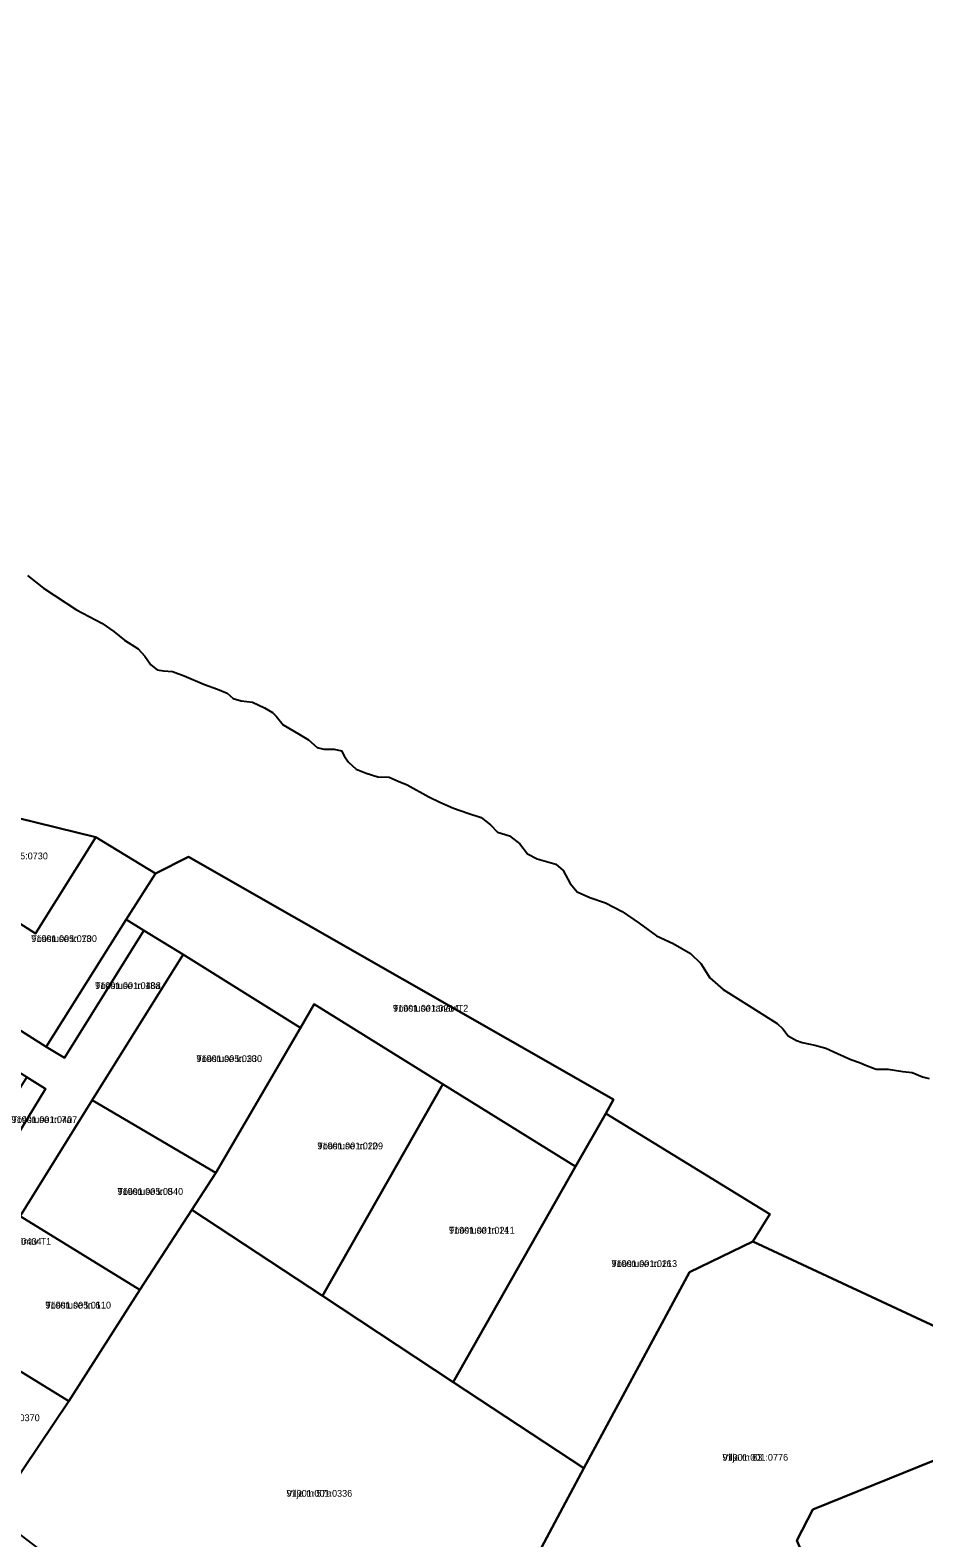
# Model space of a CAD drawing. Extents: x 675810 to 681273, y 6411190 to 6417565.
# Drawn here: x 679212.9 to 679410.2, y 6415637.7 to 6415970.5 of the extents above; entities that cross this region are included whole.
import ezdxf

# ---------------------------------------------------------------- set-up
doc = ezdxf.new("R2010")
doc.units = 0
for name, color, linetype in [('L_AADRESS', 7, 'Continuous'), ('PIIR', 7, 'Continuous'), ('TUNNUS', 7, 'Continuous')]:
    doc.layers.add(name, color=color, linetype=linetype)

msp = doc.modelspace()

# ---------------------------------------------------------------- linework, layer by layer
at = {"layer": 'PIIR'}
for points in [[(679418.32, 6415681.66), (679372.45, 6415703.1), (679376.15, 6415709.11), (679339.93, 6415731.36), (679341.68, 6415734.46), (679247.81, 6415787.97), (679240.52, 6415784.31), (679227.34, 6415792.31), (679201.2, 6415798.72), (679202.38, 6415803.59), (679204.44, 6415812.13), (679165.65, 6415822.55), (679175.65, 6415842.58), (679168.11, 6415879.95), (679127.82, 6415898.47), (679110.64, 6415865.76), (679105.26, 6415855.66), (678938.35, 6415931.63), (678872.23, 6415963.49), (678840.09, 6415967.49), (678816.91, 6415970.45)], [(679212.29, 6415850.08), (679215.84, 6415847.26), (679223.07, 6415842.49), (679228.71, 6415839.55), (679231.35, 6415837.72), (679233.71, 6415835.82), (679236.68, 6415833.88), (679238.2, 6415832.28), (679239.5, 6415830.35), (679240.87, 6415829.29), (679242.32, 6415829.02), (679244.28, 6415828.89), (679246.87, 6415827.94), (679251.36, 6415826.01), (679254.2, 6415825), (679256.36, 6415824.12), (679257.65, 6415822.94), (679259.46, 6415822.42), (679261.98, 6415822.13), (679264.57, 6415820.91), (679266.39, 6415819.86), (679267.15, 6415819.07), (679268.72, 6415817.14), (679272.1, 6415815.17), (679274.35, 6415813.79), (679276.26, 6415812.14), (679277.72, 6415811.74), (679280.01, 6415811.79), (679281.6, 6415811.41), (679282.25, 6415810.17), (679283.16, 6415808.91), (679284.87, 6415807.34), (679287.02, 6415806.45), (679289.61, 6415805.63), (679292.11, 6415805.58), (679294.14, 6415804.67), (679296.09, 6415803.87), (679300.92, 6415801.24), (679303.32, 6415800.04), (679306.34, 6415798.75), (679309.5, 6415797.63), (679312.44, 6415796.71), (679314.47, 6415795.06), (679316.07, 6415793.47), (679318.72, 6415792.65), (679320.98, 6415790.86), (679322.7, 6415788.65), (679324.82, 6415787.53), (679328.93, 6415786.38), (679330.54, 6415784.96), (679332.12, 6415782.11), (679333.67, 6415780.3), (679336.42, 6415779), (679339.88, 6415777.87), (679343.56, 6415775.95), (679347.36, 6415773.38), (679351.16, 6415770.56), (679354.83, 6415768.85), (679358.63, 6415766.64), (679360.96, 6415764.43), (679362.92, 6415761.25), (679365.86, 6415758.68), (679371.62, 6415755.12), (679377.79, 6415751.24), (679379.06, 6415750.02), (679380.25, 6415748.51), (679382.07, 6415747.45), (679383.28, 6415747.03), (679386.09, 6415746.46), (679388.56, 6415745.79), (679391.14, 6415744.57), (679394.08, 6415743.26), (679395.95, 6415742.62), (679397.53, 6415741.92), (679399.66, 6415741.13), (679402.3, 6415741.11), (679405.51, 6415740.58), (679407.64, 6415740.36), (679409.9, 6415739.42), (679411.38, 6415739.08)]]:
    msp.add_lwpolyline(points, dxfattribs=at)
for points in [[(679227.34, 6415792.31), (679214.01, 6415771.08), (679201.32, 6415779.15), (679199.24, 6415775.74), (679173.32, 6415791.71), (679181.33, 6415803.8), (679201.2, 6415798.72)], [(679240.52, 6415784.31), (679234.07, 6415774.13), (679216.42, 6415746.08), (679190.94, 6415762.16), (679199.24, 6415775.74), (679201.32, 6415779.15), (679214.01, 6415771.08), (679227.34, 6415792.31)], [(679234.07, 6415774.13), (679240.52, 6415784.31), (679247.81, 6415787.97), (679341.68, 6415734.46), (679339.93, 6415731.36), (679333.27, 6415719.67), (679303.99, 6415737.83), (679275.59, 6415755.46), (679272.55, 6415750.27), (679246.64, 6415766.45), (679237.97, 6415771.73)], [(679220.47, 6415743.64), (679216.42, 6415746.08), (679234.07, 6415774.13), (679237.97, 6415771.73)], [(679163.58, 6415633.02), (679155.1, 6415638.2), (679169.58, 6415662.1), (679187.29, 6415690.12), (679183.17, 6415692.68), (679188.31, 6415701.04), (679192.5, 6415698.51), (679205.47, 6415719.21), (679216.26, 6415736.76), (679212.15, 6415739.39), (679186.52, 6415755.32), (679188.68, 6415758.8), (679190.94, 6415762.16), (679216.42, 6415746.08), (679220.47, 6415743.64), (679237.97, 6415771.73), (679246.64, 6415766.45), (679226.57, 6415734.31), (679210.69, 6415708.71), (679208.62, 6415705.42), (679195.3, 6415683.87), (679179.77, 6415659.03)], [(679253.82, 6415718.26), (679226.57, 6415734.31), (679246.64, 6415766.45), (679272.55, 6415750.27)], [(679253.82, 6415718.26), (679272.55, 6415750.27), (679275.59, 6415755.46), (679303.99, 6415737.83), (679277.39, 6415691.1), (679248.54, 6415710.1)], [(679205.47, 6415719.21), (679201.22, 6415721.97), (679212.15, 6415739.39), (679216.26, 6415736.76)], [(679277.39, 6415691.1), (679303.99, 6415737.83), (679333.27, 6415719.67), (679306.26, 6415672.05)], [(679210.69, 6415708.71), (679226.57, 6415734.31), (679253.82, 6415718.26), (679248.54, 6415710.1), (679237.06, 6415692.46)], [(679333.27, 6415719.67), (679339.93, 6415731.36), (679376.15, 6415709.11), (679372.45, 6415703.1), (679358.43, 6415696.3), (679335.12, 6415653.05), (679306.26, 6415672.05)], [(679237.06, 6415692.46), (679248.54, 6415710.1), (679277.39, 6415691.1), (679306.26, 6415672.05), (679335.12, 6415653.05), (679316.48, 6415618.21), (679301.31, 6415612.53), (679223.54, 6415583.42), (679222.37, 6415587.28), (679259.47, 6415601.16), (679204.65, 6415643.01), (679221.39, 6415667.86)], [(679237.06, 6415692.46), (679221.39, 6415667.86), (679195.3, 6415683.87), (679208.62, 6415705.42), (679210.69, 6415708.71)], [(679315.12, 6415578.53), (679312.49, 6415585.02), (679301.31, 6415612.53), (679316.48, 6415618.21), (679335.12, 6415653.05), (679358.43, 6415696.3), (679372.45, 6415703.1), (679418.32, 6415681.66), (679430.12, 6415661.86), (679422.64, 6415658.86), (679385.66, 6415643.95), (679382.13, 6415637.11), (679386.45, 6415627.17), (679364.62, 6415608.64), (679330.4, 6415584.06)], [(679382.13, 6415637.11), (679385.66, 6415643.95), (679422.64, 6415658.86), (679441.17, 6415610.84), (679451.07, 6415550.02), (679488.34, 6415569.79), (679512.23, 6415582.5), (679498.76, 6415612.14), (679465.54, 6415675.07), (679495.71, 6415687.16), (679503.28, 6415675), (679623.83, 6415611.22), (679564.12, 6415577.12), (679525.51, 6415556.28), (679439.43, 6415509.13), (679424.12, 6415535.76), (679415.7, 6415550.54), (679385.8, 6415612.44), (679391.82, 6415614.98), (679386.45, 6415627.17)], [(679195.3, 6415683.87), (679221.39, 6415667.86), (679204.65, 6415643.01), (679179.77, 6415659.03)]]:
    msp.add_lwpolyline(points, close=True, dxfattribs=at)

# ---------------------------------------------------------------- texts
at = {"layer": 'L_AADRESS'}
for s, p in [('Tööstuse tn 13', (679213.1, 6415769.19)), ('Tööstuse tn 13a', (679227.2, 6415758.82)), ('Tööstuse tänav T2', (679292.97, 6415753.82)), ('Tööstuse tn 10', (679249.56, 6415742.7)), ('Tööstuse tn 7a', (679208.74, 6415729.24)), ('Tööstuse tn 12', (679276.27, 6415723.44)), ('Tööstuse tn 8', (679232.13, 6415713.38)), ('Tööstuse tn 14', (679305.33, 6415704.83)), ('Tööstuse tänav T1', (679200.87, 6415702.37)), ('Tööstuse tn 16', (679341.2, 6415697.46)), ('Tööstuse tn 6', (679216.21, 6415688.29)), ('Vilja tn 63', (679365.71, 6415654.7)), ('Vilja tn 57a', (679269.47, 6415646.76))]:
    msp.add_text(s, height=1.5, dxfattribs=at).set_placement(p)
at = {"layer": 'TUNNUS'}
for s, p in [('91901:005:0730', (679202.27, 6415787.44)), ('91901:005:0700', (679213.1, 6415769.19)), ('91901:001:0408', (679227.2, 6415758.82)), ('91901:001:0214', (679292.97, 6415753.82)), ('91901:005:0330', (679249.56, 6415742.7)), ('91901:001:0407', (679208.74, 6415729.24)), ('91901:001:0209', (679276.27, 6415723.44)), ('91901:005:0540', (679232.13, 6415713.38)), ('91901:001:0211', (679305.33, 6415704.83)), ('91901:001:0404', (679200.87, 6415702.37)), ('91901:001:0213', (679341.2, 6415697.46)), ('91901:005:0110', (679216.21, 6415688.29)), ('91901:005:0370', (679200.47, 6415663.44)), ('91901:001:0776', (679365.71, 6415654.7)), ('91901:001:0336', (679269.47, 6415646.76))]:
    msp.add_text(s, height=1.5, dxfattribs=at).set_placement(p)

doc.saveas('drawing.dxf')
